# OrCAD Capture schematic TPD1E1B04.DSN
size A; title: TPD1E1B04 1-Channel ESD Protection Diode; rev: 1.0; note: Datasheet: SLVSDL0
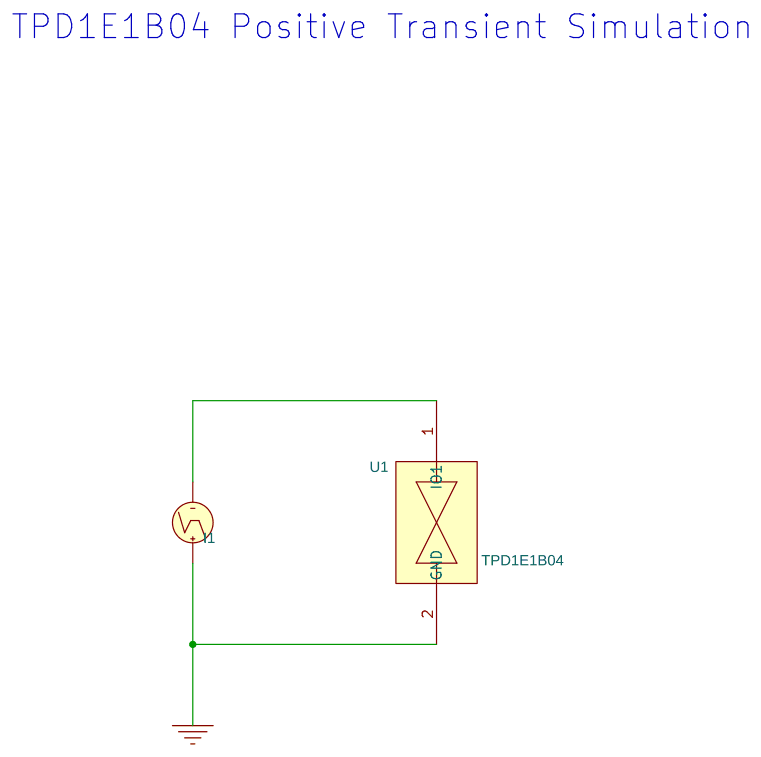
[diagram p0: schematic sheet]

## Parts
I1  IPWL_GENERIC
U1  TPD1E1B04

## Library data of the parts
I1 = IPWL_GENERIC: AppProp: No_reps$POINTS_TYPE_PWL$0$0; FIRST_NPAIRS: 0n 0 0.8n 30 6n 8 9.5n 12.5 10n 13 18n 16 22n 16 25n 16 60n 9 72n 7 82n 5.3 150n 0; PSpiceTemplate: I^@REFDES %+ %- ?DC|DC @DC| ?AC|AC @AC| PWL ?TSF|TIME_SCALE_FACTOR=@TSF| ?VSF|VALUE_SCALE_FACTOR=@VSF| ?REPEAT_VALUE| \n+ REPEAT FOR @REPEAT_VALUE| \n+ @FIRST_NPAIRS ?SECOND_NPAIRS|\n+ @SECOND_NPAIRS ?THIRD_NPAIRS/\n+ @THIRD_NPAIRS/| ?REPEAT_VALUE| \n+ ENDREPEAT|
U1 = TPD1E1B04

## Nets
0: I1.1(+) U1.2(GND)
N02999: I1.2(-) U1.1(IO1)

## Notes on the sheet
- TPD1E1B04 Positive Transient Simulation
